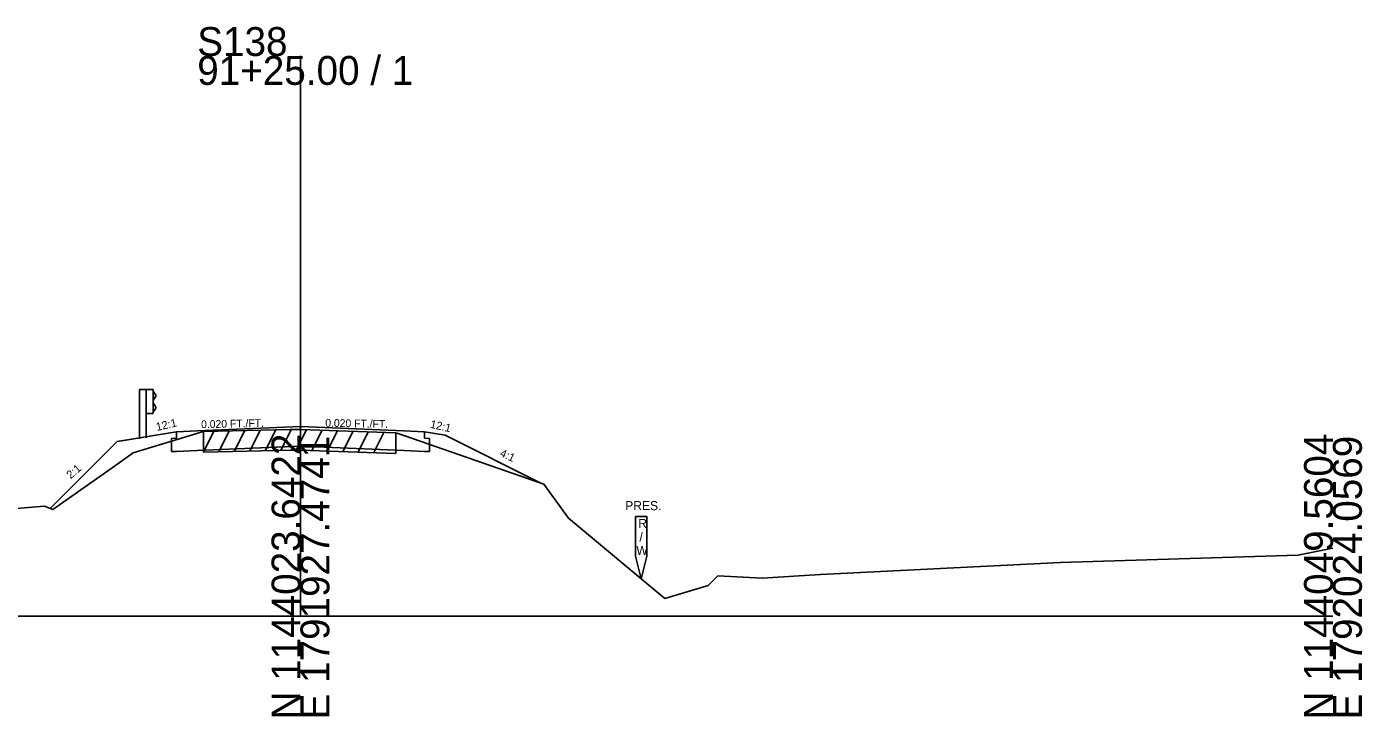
# Model space of a CAD drawing. Extents: x -26 to 1203, y -10 to 19606.
# Drawn here: x 1073.5 to 1202.8, y 2490.3 to 2557.1 of the extents above; entities that cross this region are included whole.
import ezdxf

# ---------------------------------------------------------------- set-up
doc = ezdxf.new("R2010")
doc.units = 0
for name, color, linetype in [('RD_EX_Driveway', 7, 'Continuous'), ('RD_GPK_XS_Cell', 7, 'Continuous'), ('RD_XS_Base', 7, 'Continuous'), ('RD_XS_EarthShd', 7, 'Continuous'), ('RD_XS_ExGround', 7, 'Continuous'), ('RD_XS_ExPaveRet', 7, 'Continuous'), ('RD_XS_ExRW', 7, 'Continuous'), ('RD_XS_GR', 7, 'Continuous'), ('RD_XS_Pave', 7, 'Continuous'), ('RD_XS_TX_Slope', 7, 'Continuous')]:
    doc.layers.add(name, color=color, linetype=linetype)

msp = doc.modelspace()

# ---------------------------------------------------------------- linework, layer by layer
at = {"layer": 'RD_GPK_XS_Cell'}
for p, q in [((1100, 2500), (1100, 2554.28)), ((1000, 2500), (1100, 2500)), ((1100, 2500), (1200, 2500))]:
    msp.add_line(p, q, dxfattribs=at)
at = {"layer": 'RD_XS_Base'}
for p, q in [((1088, 2517.24), (1088, 2517.88)), ((1112, 2517.24), (1112, 2517.88)), ((1088, 2517.24), (1087.5, 2517.22)), ((1087.5, 2515.95), (1087.5, 2517.22)), ((1088, 2515.97), (1090, 2516.05)), ((1090, 2516.05), (1100, 2516.47)), ((1110, 2516.05), (1100, 2516.47)), ((1112, 2515.97), (1110, 2516.05)), ((1112, 2517.24), (1112.5, 2517.22)), ((1112.5, 2515.95), (1112.5, 2517.22)), ((1088, 2515.97), (1087.5, 2515.95)), ((1112, 2515.97), (1112.5, 2515.95))]:
    msp.add_line(p, q, dxfattribs=at)
at = {"layer": 'RD_XS_EarthShd'}
for p, q in [((1086, 2517.54), (1082.25, 2516.92)), ((1086, 2517.54), (1082.5, 2516.96)), ((1088, 2517.88), (1086, 2517.54)), ((1112, 2517.88), (1114, 2517.54)), ((1114, 2517.54), (1123.22, 2512.93)), ((1075.77, 2510.44), (1082.25, 2516.92))]:
    msp.add_line(p, q, dxfattribs=at)
at = {"layer": 'RD_XS_ExGround'}
msp.add_lwpolyline([(1067.1, 2510), (1075.19, 2510.65), (1076.02, 2510.34), (1081.75, 2514.37), (1083.79, 2515.83), (1089.95, 2517.69), (1090.59, 2517.91), (1099, 2518.08), (1099.53, 2518.09), (1100, 2518.08), (1109.24, 2517.78), (1110.11, 2517.48), (1123.57, 2512.81), (1125.97, 2509.51), (1135.29, 2501.73), (1139.47, 2502.98), (1140.43, 2503.93), (1144.71, 2503.7), (1150.36, 2504.03), (1173.62, 2505.21), (1196.61, 2505.91), (1200, 2506.59)], dxfattribs=at)
at = {"layer": 'RD_XS_ExPaveRet'}
for p, q in [((1090.59, 2515.91), (1091.6, 2517.93)), ((1090.59, 2515.91), (1090.59, 2517.91)), ((1092.09, 2515.94), (1093.1, 2517.96)), ((1093.59, 2515.97), (1094.6, 2517.99)), ((1095.09, 2516), (1096.1, 2518.02)), ((1096.59, 2516.03), (1097.6, 2518.05)), ((1098.09, 2516.06), (1099.1, 2518.08)), ((1099.59, 2516.09), (1100.57, 2518.06)), ((1101.09, 2516.04), (1102.07, 2518.01)), ((1102.59, 2515.99), (1103.57, 2517.96)), ((1104.09, 2515.94), (1105.07, 2517.91)), ((1105.59, 2515.9), (1106.57, 2517.86)), ((1107.09, 2515.85), (1108.07, 2517.81)), ((1109.24, 2517.78), (1109.24, 2515.78)), ((1090.59, 2515.91), (1099, 2516.08)), ((1099, 2516.08), (1099.53, 2516.09)), ((1099.53, 2516.09), (1100, 2516.08)), ((1100, 2516.08), (1109.24, 2515.78))]:
    msp.add_line(p, q, dxfattribs=at)
at = {"layer": 'RD_XS_ExRW'}
msp.add_lwpolyline([(1132.45, 2509.66), (1133.55, 2509.66), (1133.55, 2505.83), (1133, 2503.64), (1132.45, 2505.83)], close=True, dxfattribs=at)
at = {"layer": 'RD_XS_GR'}
for p, q in [((1084.4, 2521.96), (1084.4, 2517.19)), ((1085.06, 2521.96), (1084.4, 2521.96)), ((1085.06, 2521.96), (1085.06, 2517.3)), ((1085.73, 2521.96), (1085.06, 2521.96)), ((1085.73, 2519.63), (1085.73, 2521.96)), ((1085.73, 2521.81), (1086, 2521.41)), ((1086, 2521.31), (1085.73, 2520.91)), ((1086, 2521.41), (1086, 2521.31)), ((1086, 2520.27), (1085.73, 2520.67)), ((1085.73, 2519.77), (1086, 2520.17)), ((1086, 2520.17), (1086, 2520.27)), ((1085.73, 2519.63), (1085.06, 2519.63))]:
    msp.add_line(p, q, dxfattribs=at)
at = {"layer": 'RD_XS_Pave'}
for p, q in [((1088, 2517.88), (1090, 2517.96)), ((1090, 2517.96), (1100, 2518.37)), ((1110, 2517.96), (1100, 2518.37)), ((1112, 2517.88), (1110, 2517.96))]:
    msp.add_line(p, q, dxfattribs=at)

# ---------------------------------------------------------------- texts
at = {"layer": 'RD_EX_Driveway'}
msp.add_text('548.04', height=0.0975, rotation=90, dxfattribs=at).set_placement((1100.1, 2518.08))
at = {"layer": 'RD_GPK_XS_Cell'}
for s, p in [('S138', (1090, 2554.28)), ('91+25.00 / 1', (1090, 2551.48))]:
    msp.add_text(s, height=2.8, dxfattribs=at).set_placement(p)
for s, p in [('N 1144023.6422', (1100, 2490)), ('E 1791927.4741', (1102.8, 2490)), ('N 1144049.5604', (1200, 2490)), ('E 1792024.0569', (1202.8, 2490))]:
    msp.add_text(s, height=2.8, rotation=90, dxfattribs=at).set_placement(p)
at = {"layer": 'RD_XS_ExRW'}
for s, p in [('PRES.', (1131.45, 2510.28)), ('R', (1132.71, 2508.56)), ('/', (1132.83, 2507.25)), ('W', (1132.53, 2505.94))]:
    msp.add_text(s, height=0.875, dxfattribs=at).set_placement(p)
at = {"layer": 'RD_XS_TX_Slope'}
for s, height, rotation, p in [('12:1', 0.778, 12.7511, (1086.1, 2517.95)), ('0.020 FT./FT.', 0.7518, 1.1916, (1090.38, 2518.22)), ('0.020 FT./FT.', 0.7518, 358.8084, (1102.39, 2518.37)), ('12:1', 0.778, 347.2489, (1112.51, 2518.27)), ('4:1', 0.778, 335.081, (1119.24, 2515.54)), ('2:1', 0.778, 40.6589, (1077.74, 2513.27))]:
    msp.add_text(s, height=height, rotation=rotation, dxfattribs=at).set_placement(p)

doc.saveas('drawing.dxf')
